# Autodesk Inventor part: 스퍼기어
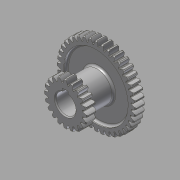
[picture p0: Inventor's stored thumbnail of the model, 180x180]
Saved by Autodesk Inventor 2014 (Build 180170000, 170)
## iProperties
Created: 2015-09
Part Number: 스퍼기어
Material: 강철, 연강
Document SubType Name: Modeling
Designer: mduedu
Density: 7.86 g/cm^3
Mass: 345.726 g
Surface Area: 225.641 cm^2
Volume: 43.9855 cm^3
Appearance: 강철
Author: mduedu
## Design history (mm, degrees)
sketch "스케치1"
  geometry: C1 r 38 at (0, 0); C2 r 40 at (0, 0); C3 r 35.5 at (0, 0); 1 further point
  constraints: 3 centre point, 3 coincident
  dimensions: "d0" = 76 diameter of C1; "d2" = 2 radial gap between concentric circles of C2 C1; "d3" = 71 diameter of C3 (computed from d0)
extrude "돌출1" new body sketch "스케치1" stored distance "d4" = 10; taper "d5" = 0 deg
sketch "스케치2"
  geometry: L1 (0, 35.5)-(0, -35.5); L2 (0, 0)-(40, 0); L3 (0, 0.57)-(39.996, 0.57); L4 (0, 1.57)-(39.969, 1.57); L5 (0, 2.07)-(39.946, 2.07); A1 r 35.5 centre (0, 0) between (0, 35.5) and (0, -35.5) reference; A2 r 40 centre (0, 0) between (40, 0) and (39.946, 2.07) reference; A3 r 9.234 centre (34.93, -7.149) between (39.996, 0.57) and (35.44, 2.07); A4 r 9.234 centre (34.93, 7.149) between (35.44, -2.07) and (39.996, -0.57); A5 r 40 centre (0, 0) between (39.996, -0.57) and (39.996, 0.57); A6 r 35.5 centre (0, 0) between (35.44, -2.07) and (35.44, 2.07); 4 further points
  constraints: 16 point on circle, 10 end point, 6 point on line, 4 centre point, 3 coincident, 3 parallel, 3 symmetric about line, 2 midpoint, 1 perpendicular, 1 vertical, 3 other
  dimensions: "d6" = 0.5 distance between parallel lines of L4 L5; "d8" = 1 distance between parallel lines of L3 L4; "d9" = 1.57 distance between parallel lines of L2 L4
extrude "돌출2" join sketch "스케치2" distance "d10" = 5; taper "d12" = 0 deg; dims "d11" = 5, "d13" = 0
fillet "모깎기1" dims "d17" = 0.5
chamfer "모따기1" distance "d21" = 1; stored, may be unused: second distance "d22" = 2, angle "d23" = 45 deg
sketch "스케치3"
  geometry: C1 r 32.5 at (0, 0); C2 r 15 at (0, 0); 1 further point
  constraints: 2 centre point, 2 coincident
  dimensions: "d27" = 65 diameter of C1; "d28" = 30 diameter of C2
extrude "돌출3" cut sketch "스케치3" distance "d29" = 3; taper "d30" = 0 deg
fillet "모깎기2" dims "d31" = 2
node "작업 평면2"
  node "작업 평면1"
sketch "스케치4"
  geometry: C1 r 15 at (0, 0) reference; 1 further point
extrude "돌출4" join sketch "스케치4" stored distance "d34" = 3; taper "d35" = 0 deg
sketch "스케치5"
  geometry: C1 r 17.5 at (0, 0); C2 r 20 at (0, 0); C3 r 22 at (0, 0); 1 further point
  constraints: 3 centre point, 3 coincident
  dimensions: "d36" = 40 diameter of C2; "d38" = 2 radial gap between concentric circles of C2 C3; "d39" = 35 diameter of C1 (= d36 - 2.5 x d38)
extrude "돌출6" join sketch "스케치5" distance "d46" = 10; taper "d47" = 0 deg
sketch "스케치6"
  geometry: L1 (0, 0)-(0, 22); L2 (-17.5, 0)-(17.5, 0); L3 (-0.57, 0)-(-0.57, 21.993); L4 (-1.57, 0)-(-1.57, 21.944); L5 (-2.07, 0)-(-2.07, 21.902); A1 r 22 centre (0, 0) between (0, 22) and (-0.57, 21.993) reference; A2 r 17.5 centre (0, 0) between (-17.5, 0) and (17.5, 0) reference; A3 r 9.431 centre (7.348, 16.868) between (-0.57, 21.993) and (-2.07, 17.377); A4 r 9.431 centre (-7.348, 16.868) between (2.07, 17.377) and (0.57, 21.993); A5 r 17.5 centre (0, 0) between (2.07, 17.377) and (-2.07, 17.377); A6 r 22 centre (0, 0) between (0.57, 21.993) and (-0.57, 21.993); 4 further points
  constraints: 16 point on circle, 10 end point, 5 point on line, 4 centre point, 3 coincident, 3 symmetric about line, 2 parallel, 2 perpendicular, 1 midpoint, 1 vertical, 3 other
  dimensions: "d40" = 0.5 distance between parallel lines of L4 L5; "d42" = 1 distance between parallel lines of L3 L4; "d43" = 1.57 distance between parallel lines of L1 L4
extrude "돌출5" join sketch "스케치6" distance "d44" = 10; taper "d45" = 0 deg
fillet "모깎기3" dims "d48" = 0.5
chamfer "모따기2" distance "d49" = 1; stored, may be unused: second distance "d50" = 2, angle "d51" = 45 deg
sketch "스케치7"
  geometry: C1 r 10 at (0, 0); 1 further point
  constraints: 1 centre point, 1 coincident
  dimensions: "d55" = 20 diameter of C1
extrude "돌출7" cut sketch "스케치7" stored distance "d56" = 10; taper "d57" = 0 deg
sketch "스케치8"
  geometry: L1 (-9.539, -3)-(-12.8, -3); L2 (-12.8, -3)-(-12.8, 3); L3 (-12.8, 3)-(-9.539, 3); L4 (-9.539, 3)-(-9.539, -3); A1 r 10 centre (0, 0) between (-9.539, -3) and (-9.539, 3) reference; 2 further points
  constraints: 8 end point, 3 point on circle, 2 parallel, 1 horizontal, 1 horizontal alignment, 1 perpendicular
  dimensions: "d58" = 6 distance of L1.end L2.end; "d60" = 22.8 distance from line of point (10, 0) L2
extrude "돌출8" cut sketch "스케치8" stored distance "d61" = 10; taper "d62" = 0 deg
chamfer "모따기3" distance "d63" = 1; stored, may be unused: second distance "d64" = 2, angle "d65" = 45 deg
fillet "모깎기4" dims "d66" = 2
node "솔리드1"
pattern_circular "원형 패턴3" dims "d25" = 360 deg
mirror "대칭1"
pattern_circular "원형 패턴4" dims "d53" = 360 deg
other parameters: "d32" = 9
